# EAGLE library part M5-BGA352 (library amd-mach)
AMD MACH SERIES
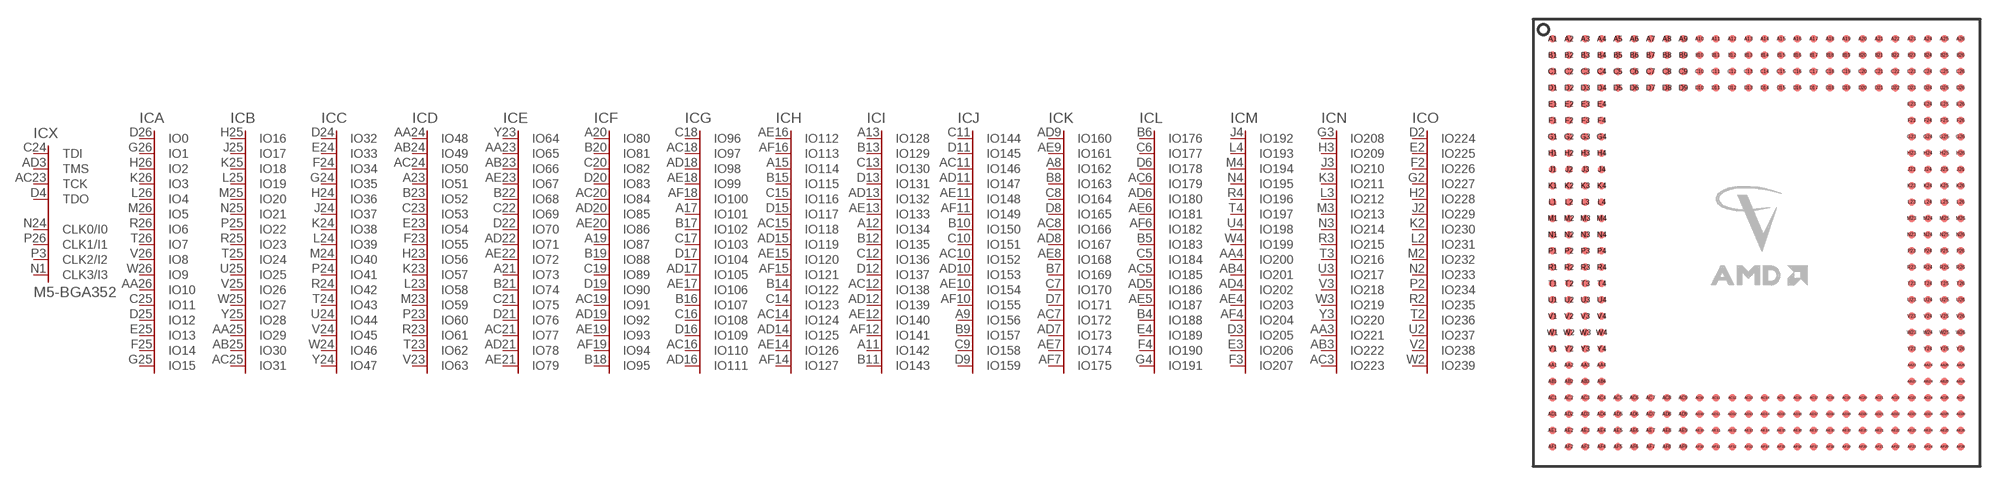
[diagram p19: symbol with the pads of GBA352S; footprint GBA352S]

Designator prefix IC; gates X=M5-CTRL A=IO15 B=IO31 C=IO47 D=IO63 E=IO79 F=IO95 G=IO111 H=IO127 I=IO143 J=IO159 K=IO175 L=IO191 M=IO207 N=IO223 O=IO239 P=IO255 V1=VCC V2=VCC V3=VCC V4=VCC V5=VCC V6=VCC V7=VCC V8=VCC V9=VCC V10=VCC V11=VCC V12=VCC V13=VCC V14=VCC V15=VCC V16=VCC V17=VCC V18=VCC V19=VCC V20=VCC G1=GND G2=GND G3=GND G4=GND G5=GND G6=GND G7=GND G8=GND G9=GND G10=GND G11=GND G12=GND G13=GND G14=GND G15=GND G16=GND G17=GND G18=GND G19=GND G20=GND G21=GND G22=GND G23=GND NC1=NC NC2=NC NC3=NC NC4=NC NC5=NC NC6=NC NC7=NC NC8=NC NC9=NC NC10=NC NC11=NC NC12=NC NC13=NC NC14=NC NC15=NC NC16=NC NC17=NC NC18=NC NC19=NC NC20=NC NC21=NC NC22=NC NC23=NC NC24=NC NC25=NC NC26=NC NC27=NC NC28=NC NC29=NC NC30=NC G24=GND G25=GND G26=GND G27=GND G28=GND G29=GND G30=GND G31=GND G32=GND NC31=NC NC32=NC NC33=NC NC34=NC G33=GND G34=GND

## M5-BGA352 (OC_FARNELL: unknown; OC_NEWARK: unknown)  [GBA352S]
A1  NC1:NC  nc
A2  NC2:NC  nc
A3  G1:GND  pwr
A4  NC3:NC  nc
A5  G2:GND  pwr
A6  NC4:NC  nc
A7  G3:GND  pwr
A8  K:IO162
A9  J:IO156
A10  G4:GND  pwr
A11  I:IO142
A12  I:IO134
A13  I:IO128
A14  G5:GND  pwr
A15  H:IO114
A16  NC5:NC  nc
A17  G:IO101
A18  G6:GND  pwr
A19  F:IO87
A20  F:IO80
A21  E:IO73
A22  G7:GND  pwr
A23  D:IO51
A24  NC6:NC  nc
A25  G8:GND  pwr
A26  NC7:NC  nc
AA1  G9:GND  pwr
AA2  P:IO241
AA3  N:IO221
AA4  M:IO200
AA23  E:IO65
AA24  D:IO48
AA25  B:IO29
AA26  A:IO10
AB1  NC8:NC  nc
AB2  P:IO242
AB3  N:IO222
AB4  M:IO201
AB23  E:IO66
AB24  D:IO49
AB25  B:IO30
AB26  NC9:NC  nc
AC1  P:IO255
AC2  P:IO243
AC3  N:IO223
AC4  V1:VCC  pwr
AC5  L:IO185
AC6  L:IO179
AC7  K:IO172
AC8  K:IO166
AC9  V2:VCC  pwr
AC10  J:IO152
AC11  J:IO146
AC12  I:IO138
AC13  V3:VCC  pwr
AC14  H:IO124
AC15  H:IO118
AC16  G:IO110
AC17  V4:VCC  pwr
AC18  G:IO97
AC19  F:IO91
AC20  F:IO84
AC21  E:IO77
AC22  V5:VCC  pwr
AC23  X:TCK  in
AC24  D:IO50
AC25  B:IO31
AC26  G10:GND  pwr
AD1  G11:GND  pwr
AD2  P:IO244
AD3  X:TMS  in
AD4  M:IO202
AD5  L:IO186
AD6  L:IO180
AD7  K:IO173
AD8  K:IO167
AD9  K:IO160
AD10  J:IO153
AD11  J:IO147
AD12  I:IO139
AD13  I:IO132
AD14  H:IO125
AD15  H:IO119
AD16  G:IO111
AD17  G:IO105
AD18  G:IO98
AD19  F:IO92
AD20  F:IO85
AD21  E:IO78
AD22  E:IO71
AD23  NC10:NC  nc
AD24  NC11:NC  nc
AD25  NC12:NC  nc
AD26  NC13:NC  nc
AE1  NC14:NC  nc
AE2  G12:GND  pwr
AE3  NC15:NC  nc
AE4  M:IO203
AE5  L:IO187
AE6  L:IO181
AE7  K:IO174
AE8  K:IO168
AE9  K:IO161
AE10  J:IO154
AE11  J:IO148
AE12  I:IO140
AE13  I:IO133
AE14  H:IO126
AE15  H:IO120
AE16  H:IO112
AE17  G:IO106
AE18  G:IO99
AE19  F:IO93
AE20  F:IO86
AE21  E:IO79
AE22  E:IO72
AE23  E:IO67
AE24  G13:GND  pwr
AE25  NC16:NC  nc
AE26  NC17:NC  nc
AF1  NC18:NC  nc
AF2  G14:GND  pwr
AF3  NC19:NC  nc
AF4  M:IO204
AF5  G15:GND  pwr
AF6  L:IO182
AF7  K:IO175
AF8  NC20:NC  nc
AF9  G16:GND  pwr
AF10  J:IO155
AF11  J:IO149
AF12  I:IO141
AF13  G17:GND  pwr
AF14  H:IO127
AF15  H:IO121
AF16  H:IO113
AF17  G18:GND  pwr
AF18  G:IO100
AF19  F:IO94
AF20  G19:GND  pwr
AF21  NC21:NC  nc
AF22  G20:GND  pwr
AF23  NC22:NC  nc
AF24  G21:GND  pwr
AF25  NC23:NC  nc
AF26  NC24:NC  nc
B1  NC25:NC  nc
B2  NC26:NC  nc
B3  G22:GND  pwr
B4  L:IO188
B5  L:IO183
B6  L:IO176
B7  K:IO169
B8  K:IO163
B9  J:IO157
B10  J:IO150
B11  I:IO143
B12  I:IO135
B13  I:IO129
B14  H:IO122
B15  H:IO115
B16  G:IO107
B17  G:IO102
B18  F:IO95
B19  F:IO88
B20  F:IO81
B21  E:IO74
B22  E:IO68
B23  D:IO52
B24  NC27:NC  nc
B25  G23:GND  pwr
B26  NC28:NC  nc
C1  NC29:NC  nc
C2  NC34:NC  nc
C3  NC33:NC  nc
C4  NC32:NC  nc
C5  L:IO184
C6  L:IO177
C7  K:IO170
C8  K:IO164
C9  J:IO158
C10  J:IO151
C11  J:IO144
C12  I:IO136
C13  I:IO130
C14  H:IO123
C15  H:IO116
C16  G:IO108
C17  G:IO103
C18  G:IO96
C19  F:IO89
C20  F:IO82
C21  E:IO75
C22  E:IO69
C23  D:IO53
C24  X:TDI  in
C25  A:IO11
C26  G24:GND  pwr
D1  G25:GND  pwr
D2  O:IO224
D3  M:IO205
D4  X:TDO  in
D5  V6:VCC  pwr
D6  L:IO178
D7  K:IO171
D8  K:IO165
D9  J:IO159
D10  V7:VCC  pwr
D11  J:IO145
D12  I:IO137
D13  I:IO131
D14  V8:VCC  pwr
D15  H:IO117
D16  G:IO109
D17  G:IO104
D18  V9:VCC  pwr
D19  F:IO90
D20  F:IO83
D21  E:IO76
D22  E:IO70
D23  V10:VCC  pwr
D24  C:IO32
D25  A:IO12
D26  A:IO0
E1  NC30:NC  nc
E2  O:IO225
E3  M:IO206
E4  L:IO189
E23  D:IO54
E24  C:IO33
E25  A:IO13
E26  NC31:NC  nc
F1  P:IO245
F2  O:IO226
F3  M:IO207
F4  L:IO190
F23  D:IO55
F24  C:IO34
F25  A:IO14
F26  G26:GND  pwr
G1  G27:GND  pwr
G2  O:IO227
G3  N:IO208
G4  L:IO191
G23  V11:VCC  pwr
G24  C:IO35
G25  A:IO15
G26  A:IO1
H1  P:IO246
H2  O:IO228
H3  N:IO209
H4  V12:VCC  pwr
H23  D:IO56
H24  C:IO36
H25  B:IO16
H26  A:IO2
J1  P:IO247
J2  O:IO229
J3  N:IO210
J4  M:IO192
J23  V13:VCC  pwr
J24  C:IO37
J25  B:IO17
J26  G28:GND  pwr
K1  G29:GND  pwr
K2  O:IO230
K3  N:IO211
K4  V14:VCC  pwr
K23  D:IO57
K24  C:IO38
K25  B:IO18
K26  A:IO3
L1  P:IO248
L2  O:IO231
L3  N:IO212
L4  M:IO193
L23  D:IO58
L24  C:IO39
L25  B:IO19
L26  A:IO4
M1  P:IO249
M2  O:IO232
M3  N:IO213
M4  M:IO194
M23  D:IO59
M24  C:IO40
M25  B:IO20
M26  A:IO5
N1  X:CLK3/I3  in
N2  O:IO233
N3  N:IO214
N4  M:IO195
N23  V15:VCC  pwr
N24  X:CLK0/I0  in
N25  B:IO21
N26  G30:GND  pwr
P1  G31:GND  pwr
P2  O:IO234
P3  X:CLK2/I2  in
P4  V16:VCC  pwr
P23  D:IO60
P24  C:IO41
P25  B:IO22
P26  X:CLK1/I1  in
R1  P:IO250
R2  O:IO235
R3  N:IO215
R4  M:IO196
R23  D:IO61
R24  C:IO42
R25  B:IO23
R26  A:IO6
T1  P:IO251
T2  O:IO236
T3  N:IO216
T4  M:IO197
T23  D:IO62
T24  C:IO43
T25  B:IO24
T26  A:IO7
U1  P:IO252
U2  O:IO237
U3  N:IO217
U4  M:IO198
U23  V17:VCC  pwr
U24  C:IO44
U25  B:IO25
U26  G32:GND  pwr
V1  G33:GND  pwr
V2  O:IO238
V3  N:IO218
V4  V18:VCC  pwr
V23  D:IO63
V24  C:IO45
V25  B:IO26
V26  A:IO8
W1  P:IO253
W2  O:IO239
W3  N:IO219
W4  M:IO199
W23  V19:VCC  pwr
W24  C:IO46
W25  B:IO27
W26  A:IO9
Y1  P:IO254
Y2  P:IO240
Y3  N:IO220
Y4  V20:VCC  pwr
Y23  E:IO64
Y24  C:IO47
Y25  B:IO28
Y26  G34:GND  pwr

## Footprint GBA352S (pad centres in mm)
Ball Grid Array square
smd 0.6 x 0.6: A1 -15.875,15.875; A2 -14.605,15.875; A3 -13.335,15.875; A4 -12.065,15.875; A5 -10.795,15.875; A6 -9.525,15.875; A7 -8.255,15.875; A8 -6.985,15.875; A9 -5.715,15.875; A10 -4.445,15.875; A11 -3.175,15.875; A12 -1.905,15.875; A13 -0.635,15.875; A14 0.635,15.875; A15 1.905,15.875; A16 3.175,15.875; A17 4.445,15.875; A18 5.715,15.875; A19 6.985,15.875; A20 8.255,15.875; A21 9.525,15.875; A22 10.795,15.875; A23 12.065,15.875; A24 13.335,15.875; A25 14.605,15.875; A26 15.875,15.875; AA1 -15.875,-9.525; AA2 -14.605,-9.525; AA3 -13.335,-9.525; AA4 -12.065,-9.525; AA23 12.065,-9.525; AA24 13.335,-9.525; AA25 14.605,-9.525; AA26 15.875,-9.525; AB1 -15.875,-10.795; AB2 -14.605,-10.795; AB3 -13.335,-10.795; AB4 -12.065,-10.795; AB23 12.065,-10.795; AB24 13.335,-10.795; AB25 14.605,-10.795; AB26 15.875,-10.795; AC1 -15.875,-12.065; AC2 -14.605,-12.065; AC3 -13.335,-12.065; AC4 -12.065,-12.065; AC5 -10.795,-12.065; AC6 -9.525,-12.065; AC7 -8.255,-12.065; AC8 -6.985,-12.065; AC9 -5.715,-12.065; AC10 -4.445,-12.065; AC11 -3.175,-12.065; AC12 -1.905,-12.065; AC13 -0.635,-12.065; AC14 0.635,-12.065; AC15 1.905,-12.065; AC16 3.175,-12.065; AC17 4.445,-12.065; AC18 5.715,-12.065; AC19 6.985,-12.065; AC20 8.255,-12.065; AC21 9.525,-12.065; AC22 10.795,-12.065; AC23 12.065,-12.065; AC24 13.335,-12.065; AC25 14.605,-12.065; AC26 15.875,-12.065; AD1 -15.875,-13.335; AD2 -14.605,-13.335; AD3 -13.335,-13.335; AD4 -12.065,-13.335; AD5 -10.795,-13.335; AD6 -9.525,-13.335; AD7 -8.255,-13.335; AD8 -6.985,-13.335; AD9 -5.715,-13.335; AD10 -4.445,-13.335; AD11 -3.175,-13.335; AD12 -1.905,-13.335; AD13 -0.635,-13.335; AD14 0.635,-13.335; AD15 1.905,-13.335; AD16 3.175,-13.335; AD17 4.445,-13.335; AD18 5.715,-13.335; AD19 6.985,-13.335; AD20 8.255,-13.335; AD21 9.525,-13.335; AD22 10.795,-13.335; AD23 12.065,-13.335; AD24 13.335,-13.335; AD25 14.605,-13.335; AD26 15.875,-13.335; AE1 -15.875,-14.605; AE2 -14.605,-14.605; AE3 -13.335,-14.605; AE4 -12.065,-14.605; AE5 -10.795,-14.605; AE6 -9.525,-14.605; AE7 -8.255,-14.605; AE8 -6.985,-14.605; AE9 -5.715,-14.605; AE10 -4.445,-14.605; AE11 -3.175,-14.605; AE12 -1.905,-14.605; AE13 -0.635,-14.605; AE14 0.635,-14.605; AE15 1.905,-14.605; AE16 3.175,-14.605; AE17 4.445,-14.605; AE18 5.715,-14.605; AE19 6.985,-14.605; AE20 8.255,-14.605; AE21 9.525,-14.605; AE22 10.795,-14.605; AE23 12.065,-14.605; AE24 13.335,-14.605; AE25 14.605,-14.605; AE26 15.875,-14.605; AF1 -15.875,-15.875; AF2 -14.605,-15.875; AF3 -13.335,-15.875; AF4 -12.065,-15.875; AF5 -10.795,-15.875; AF6 -9.525,-15.875; AF7 -8.255,-15.875; AF8 -6.985,-15.875; AF9 -5.715,-15.875; AF10 -4.445,-15.875; AF11 -3.175,-15.875; AF12 -1.905,-15.875; AF13 -0.635,-15.875; AF14 0.635,-15.875; AF15 1.905,-15.875; AF16 3.175,-15.875; AF17 4.445,-15.875; AF18 5.715,-15.875; AF19 6.985,-15.875; AF20 8.255,-15.875; AF21 9.525,-15.875; AF22 10.795,-15.875; AF23 12.065,-15.875; AF24 13.335,-15.875; AF25 14.605,-15.875; AF26 15.875,-15.875; B1 -15.875,14.605; B2 -14.605,14.605; B3 -13.335,14.605; B4 -12.065,14.605; B5 -10.795,14.605; B6 -9.525,14.605; B7 -8.255,14.605; B8 -6.985,14.605; B9 -5.715,14.605; B10 -4.445,14.605; B11 -3.175,14.605; B12 -1.905,14.605; B13 -0.635,14.605; B14 0.635,14.605; B15 1.905,14.605; B16 3.175,14.605; B17 4.445,14.605; B18 5.715,14.605; B19 6.985,14.605; B20 8.255,14.605; B21 9.525,14.605; B22 10.795,14.605; B23 12.065,14.605; B24 13.335,14.605; B25 14.605,14.605; B26 15.875,14.605; C1 -15.875,13.335; C2 -14.605,13.335; C3 -13.335,13.335; C4 -12.065,13.335; C5 -10.795,13.335; C6 -9.525,13.335; C7 -8.255,13.335; C8 -6.985,13.335; C9 -5.715,13.335; C10 -4.445,13.335; C11 -3.175,13.335; C12 -1.905,13.335; C13 -0.635,13.335; C14 0.635,13.335; C15 1.905,13.335; C16 3.175,13.335; C17 4.445,13.335; C18 5.715,13.335; C19 6.985,13.335; C20 8.255,13.335; C21 9.525,13.335; C22 10.795,13.335; C23 12.065,13.335; C24 13.335,13.335; C25 14.605,13.335; C26 15.875,13.335; D1 -15.875,12.065; D2 -14.605,12.065; D3 -13.335,12.065; D4 -12.065,12.065; D5 -10.795,12.065; D6 -9.525,12.065; D7 -8.255,12.065; D8 -6.985,12.065; D9 -5.715,12.065; D10 -4.445,12.065; D11 -3.175,12.065; D12 -1.905,12.065; D13 -0.635,12.065; D14 0.635,12.065; D15 1.905,12.065; D16 3.175,12.065; D17 4.445,12.065; D18 5.715,12.065; D19 6.985,12.065; D20 8.255,12.065; D21 9.525,12.065; D22 10.795,12.065; D23 12.065,12.065; D24 13.335,12.065; D25 14.605,12.065; D26 15.875,12.065; E1 -15.875,10.795; E2 -14.605,10.795; E3 -13.335,10.795; E4 -12.065,10.795; E23 12.065,10.795; E24 13.335,10.795; E25 14.605,10.795; E26 15.875,10.795; F1 -15.875,9.525; F2 -14.605,9.525; F3 -13.335,9.525; F4 -12.065,9.525; F23 12.065,9.525; F24 13.335,9.525; F25 14.605,9.525; F26 15.875,9.525; G1 -15.875,8.255; G2 -14.605,8.255; G3 -13.335,8.255; G4 -12.065,8.255; G23 12.065,8.255; G24 13.335,8.255; G25 14.605,8.255; G26 15.875,8.255; H1 -15.875,6.985; H2 -14.605,6.985; H3 -13.335,6.985; H4 -12.065,6.985; H23 12.065,6.985; H24 13.335,6.985; H25 14.605,6.985; H26 15.875,6.985; J1 -15.875,5.715; J2 -14.605,5.715; J3 -13.335,5.715; J4 -12.065,5.715; J23 12.065,5.715; J24 13.335,5.715; J25 14.605,5.715; J26 15.875,5.715; K1 -15.875,4.445; K2 -14.605,4.445; K3 -13.335,4.445; K4 -12.065,4.445; K23 12.065,4.445; K24 13.335,4.445; K25 14.605,4.445; K26 15.875,4.445; L1 -15.875,3.175; L2 -14.605,3.175; L3 -13.335,3.175; L4 -12.065,3.175; L23 12.065,3.175; L24 13.335,3.175; L25 14.605,3.175; L26 15.875,3.175; M1 -15.875,1.905; M2 -14.605,1.905; M3 -13.335,1.905; M4 -12.065,1.905; M23 12.065,1.905; M24 13.335,1.905; M25 14.605,1.905; M26 15.875,1.905; N1 -15.875,0.635; N2 -14.605,0.635; N3 -13.335,0.635; N4 -12.065,0.635; N23 12.065,0.635; N24 13.335,0.635; N25 14.605,0.635; N26 15.875,0.635; P1 -15.875,-0.635; P2 -14.605,-0.635; P3 -13.335,-0.635; P4 -12.065,-0.635; P23 12.065,-0.635; P24 13.335,-0.635; P25 14.605,-0.635; P26 15.875,-0.635; R1 -15.875,-1.905; R2 -14.605,-1.905; R3 -13.335,-1.905; R4 -12.065,-1.905; R23 12.065,-1.905; R24 13.335,-1.905; R25 14.605,-1.905; R26 15.875,-1.905; T1 -15.875,-3.175; T2 -14.605,-3.175; T3 -13.335,-3.175; T4 -12.065,-3.175; T23 12.065,-3.175; T24 13.335,-3.175; T25 14.605,-3.175; T26 15.875,-3.175; U1 -15.875,-4.445; U2 -14.605,-4.445; U3 -13.335,-4.445; U4 -12.065,-4.445; U23 12.065,-4.445; U24 13.335,-4.445; U25 14.605,-4.445; U26 15.875,-4.445; V1 -15.875,-5.715; V2 -14.605,-5.715; V3 -13.335,-5.715; V4 -12.065,-5.715; V23 12.065,-5.715; V24 13.335,-5.715; V25 14.605,-5.715; V26 15.875,-5.715; W1 -15.875,-6.985; W2 -14.605,-6.985; W3 -13.335,-6.985; W4 -12.065,-6.985; W23 12.065,-6.985; W24 13.335,-6.985; W25 14.605,-6.985; W26 15.875,-6.985; Y1 -15.875,-8.255; Y2 -14.605,-8.255; Y3 -13.335,-8.255; Y4 -12.065,-8.255; Y23 12.065,-8.255; Y24 13.335,-8.255; Y25 14.605,-8.255; Y26 15.875,-8.255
